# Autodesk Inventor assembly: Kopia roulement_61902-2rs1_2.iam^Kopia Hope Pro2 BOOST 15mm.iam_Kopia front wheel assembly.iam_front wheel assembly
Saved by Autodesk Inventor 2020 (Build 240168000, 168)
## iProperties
Created: 2017-09
Part Number: Kopia roulement_61902-2rs1_2.iam^Kopia Hope Pro2 BOOST 15mm.iam_Kopia front wheel assembly.iam_front wheel assembly
Material: Ogólny
Document SubType Name: Assembly
Designer: Tomasz
Sending System: SolidWorks 2017
Last Author: Tomasz
Last Saved: 2017-09-11
Author: Tomasz
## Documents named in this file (6)
- C:\Users\bruno\Documents\1-Cours-2020-21\1STI2D-2020-21\IT\6. Antivol\Inventor-Antivol\INVENTOR 2018_Steel Hardtail B+\Kopia roulement_61902-2rs1_2.iam^Kopia Hope Pro2 BOOST 15mm.iam_Kopia front wheel assembly.iam_front wheel assembly.iam
- C:\Users\Tomasz\Desktop\Rear Hub Motor Ebike\Kopia roulement_61902-2rs1_2_01 2.ipt^Kopia roulement_61902-2rs1_2.iam_Kopia Hope Pro2 BOOST 15mm.iam_Kopia front wheel assembly.iam_front wheel assembly.ipt
- C:\Users\Tomasz\Desktop\Rear Hub Motor Ebike\Kopia roulement_61902-2rs1_2_02 2.ipt^Kopia roulement_61902-2rs1_2.iam_Kopia Hope Pro2 BOOST 15mm.iam_Kopia front wheel assembly.iam_front wheel assembly.ipt
- C:\Users\Tomasz\Desktop\Rear Hub Motor Ebike\Kopia roulement_61902-2rs1_2_03.ipt^Kopia roulement_61902-2rs1_2.iam_Kopia Hope Pro2 BOOST 15mm.iam_Kopia front wheel assembly.iam_front wheel assembly.ipt
- C:\Users\Tomasz\Desktop\Rear Hub Motor Ebike\Kopia roulement_61902-2rs1_2_04.ipt^Kopia roulement_61902-2rs1_2.iam_Kopia Hope Pro2 BOOST 15mm.iam_Kopia front wheel assembly.iam_front wheel assembly.ipt
- C:\Users\Tomasz\Desktop\Rear Hub Motor Ebike\Kopia roulement_61902-2rs1_2_05.ipt^Kopia roulement_61902-2rs1_2.iam_Kopia Hope Pro2 BOOST 15mm.iam_Kopia front wheel assembly.iam_front wheel assembly.ipt
